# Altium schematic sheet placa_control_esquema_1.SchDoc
size A4
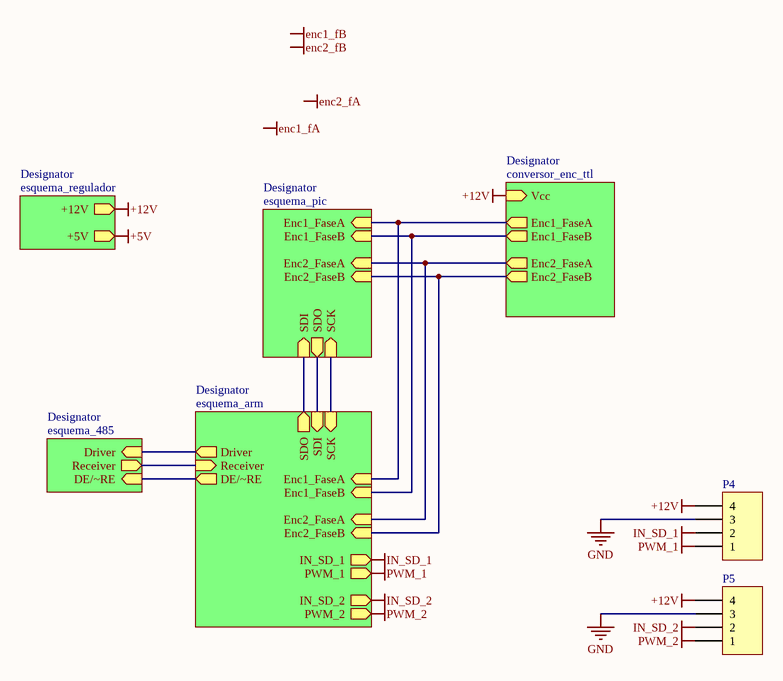
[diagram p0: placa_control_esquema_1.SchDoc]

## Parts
P4  Header 4  [HDR1X5]  (value not drawn)
P5  Header 4  [HDR1X5]  (value not drawn)

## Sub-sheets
Designator = esquema_regulador: +12V (out), +5V (out)
Designator = esquema_pic: SDI (in), SDO (out), SCK (in), Enc1_FaseA (in), Enc1_FaseB (in), Enc2_FaseA (in), Enc2_FaseB (in)
Designator = esquema_485: Driver (in), Receiver (out), DE/~RE (in)
Designator = esquema_arm: SDI (in), SDO (out), SCK (in), Enc1_FaseA (in), Enc1_FaseB (in), Enc2_FaseA (in), Enc2_FaseB (in), DE/~RE (out), Receiver (in), Driver (out), PWM_1 (out), PWM_2 (out), IN_SD_2 (out), IN_SD_1 (out)
Designator = conversor_enc_ttl: Enc1_FaseA (out), Enc1_FaseB (out), Enc2_FaseA (out), Enc2_FaseB (out), Vcc (in)

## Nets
+12V: P4.4 P5.4 ; sheet Designator/+12V, sheet Designator/Vcc
GND: P4.3 P5.3
IN_SD_1: P4.2 ; sheet Designator/IN_SD_1
IN_SD_2: P5.2 ; sheet Designator/IN_SD_2
PWM_1: P4.1 ; sheet Designator/PWM_1
PWM_2: P5.1 ; sheet Designator/PWM_2
(unnamed): sheet Designator/SDI, sheet Designator/SDO
(unnamed): sheet Designator/SDO, sheet Designator/SDI  [a separate net that carries the same name]
(unnamed): sheet Designator/SCK, sheet Designator/SCK  [a separate net that carries the same name]
(unnamed): sheet Designator/Enc1_FaseA, sheet Designator/Enc1_FaseA, sheet Designator/Enc1_FaseA  [a separate net that carries the same name]
(unnamed): sheet Designator/Enc1_FaseB, sheet Designator/Enc1_FaseB, sheet Designator/Enc1_FaseB  [a separate net that carries the same name]
(unnamed): sheet Designator/Enc2_FaseA, sheet Designator/Enc2_FaseA, sheet Designator/Enc2_FaseA  [a separate net that carries the same name]
(unnamed): sheet Designator/Enc2_FaseB, sheet Designator/Enc2_FaseB, sheet Designator/Enc2_FaseB  [a separate net that carries the same name]
(unnamed): sheet Designator/Driver, sheet Designator/Driver  [a separate net that carries the same name]
(unnamed): sheet Designator/Receiver, sheet Designator/Receiver  [a separate net that carries the same name]
(unnamed): sheet Designator/DE/~RE, sheet Designator/DE/~RE  [a separate net that carries the same name]

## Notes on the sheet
- Labels drawn without touching a wire or pin: enc1_fA, enc1_fB, enc2_fA, enc2_fB

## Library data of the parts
P4 P5 = Header 4: Header, 4-Pin; value: hdr1x5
